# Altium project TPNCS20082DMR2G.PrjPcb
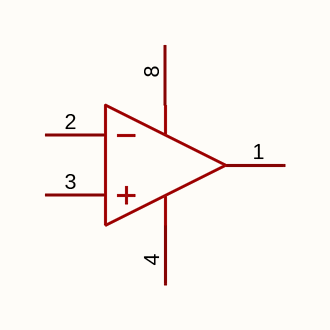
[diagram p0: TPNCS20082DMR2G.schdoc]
1 sheet, 1 parts. Net scope: global (net labels, ports and power ports of the same name join across sheets).

## Sheet TPNCS20082DMR2G.schdoc
size 127 x 101 mm

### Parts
U?  tpncs20082dmr2g  [MSOP-8_L3.0-W3.0-P0.65-LS4.9-BL]  (value not drawn)  (part A of 2)

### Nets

Not connected (* = marked no-connect by the designer): U? 1(OUT_A) 2(IN_A-) 3(IN_A+) 4(VSS) 8(VDD)

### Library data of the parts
U? = tpncs20082dmr2g: 放大器数:2;轨到轨:轨到轨输入,轨到轨输出;增益带宽积(GBW):1MHz;输入失调电压(Vos):5mV;压摆率(SR):600V/ms;输入偏置电流(Ib):10pA;; Manufacturer: TECH PUBLIC(台舟); AddInBom: yes; ModelId: bedc0aeebe0a475e87aaac88bd02a14b; ModelName: MSOP-8_L3.0-W3.0-H1.1-LS4.9-P0.65; ModelTransform: 118.11,192.913,0,0,0,0,0,0,0; Number of Channels: 2; Gain Bandwidth Product: 1MHz; Vos - Input Offset Voltage: 5mV; Input Offset Voltage Drift(Vos TC): 2uV/℃; Ib - Input Bias Current: 10pA; Input Voltage Noise Density: 20nV/√Hz@10kHz; Common Mode Rejection Ratio(CMRR): 80dB; Quiescent Current: 55uA; Output Current: 20mA; Single supply: 1.8V~5.5V; Dual Supply: -2.75V~-900mV；900mV~2.75V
